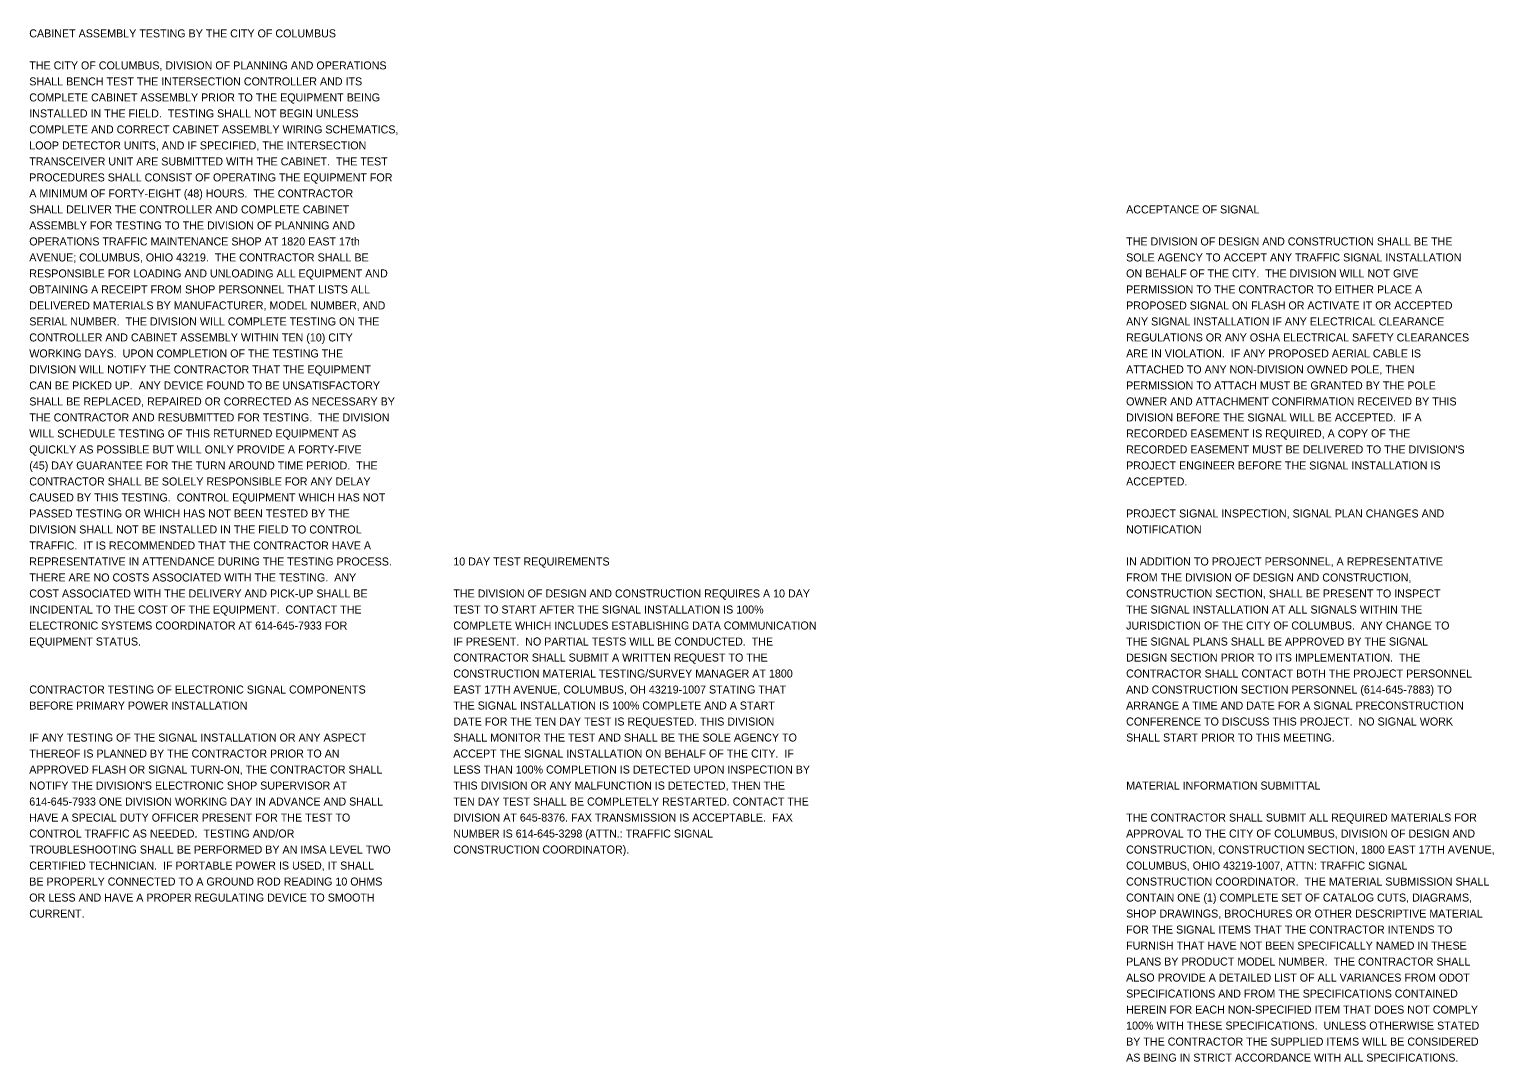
# Model space of a CAD drawing. Extents: x -62 to 50, y -16 to 14.
# Drawn here: x -62.28 to -36.65, y -4.43 to 13.63 of the extents above; entities that cross this region are included whole.
import ezdxf

# ---------------------------------------------------------------- set-up
doc = ezdxf.new("R2010")
doc.units = 0
doc.layers.add('SH_Text', color=7, linetype='Continuous')

msp = doc.modelspace()

# ---------------------------------------------------------------- texts
at = {"layer": 'SH_Text'}
for s, p in [('CABINET ASSEMBLY TESTING BY THE CITY OF COLUMBUS', (-62.277, 13.492)), ('THE CITY OF COLUMBUS, DIVISION OF PLANNING AND OPERATIONS ', (-62.277, 12.932)), ('SHALL BENCH TEST THE INTERSECTION CONTROLLER AND ITS ', (-62.277, 12.652)), ('COMPLETE CABINET ASSEMBLY PRIOR TO THE EQUIPMENT BEING ', (-62.277, 12.372)), ('INSTALLED IN THE FIELD.  TESTING SHALL NOT BEGIN UNLESS ', (-62.277, 12.092)), ('COMPLETE AND CORRECT CABINET ASSEMBLY WIRING SCHEMATICS, ', (-62.277, 11.812)), ('LOOP DETECTOR UNITS, AND IF SPECIFIED, THE INTERSECTION ', (-62.277, 11.532)), ('TRANSCEIVER UNIT ARE SUBMITTED WITH THE CABINET.  THE TEST ', (-62.277, 11.252)), ('PROCEDURES SHALL CONSIST OF OPERATING THE EQUIPMENT FOR ', (-62.277, 10.972)), ('A MINIMUM OF FORTY-EIGHT (48) HOURS.  THE CONTRACTOR ', (-62.277, 10.692)), ('SHALL DELIVER THE CONTROLLER AND COMPLETE CABINET ', (-62.277, 10.412)), ('ACCEPTANCE OF SIGNAL ', (-43.083, 10.412)), ('ASSEMBLY FOR TESTING TO THE DIVISION OF PLANNING AND ', (-62.277, 10.132)), ('OPERATIONS TRAFFIC MAINTENANCE SHOP AT 1820 EAST 17th ', (-62.277, 9.852)), ('THE DIVISION OF DESIGN AND CONSTRUCTION SHALL BE THE ', (-43.083, 9.852)), ('AVENUE; COLUMBUS, OHIO 43219.  THE CONTRACTOR SHALL BE ', (-62.277, 9.572)), ('SOLE AGENCY TO ACCEPT ANY TRAFFIC SIGNAL INSTALLATION ', (-43.083, 9.572)), ('RESPONSIBLE FOR LOADING AND UNLOADING ALL EQUIPMENT AND ', (-62.277, 9.292)), ('ON BEHALF OF THE CITY.  THE DIVISION WILL NOT GIVE ', (-43.083, 9.292)), ('OBTAINING A RECEIPT FROM SHOP PERSONNEL THAT LISTS ALL ', (-62.277, 9.012)), ('PERMISSION TO THE CONTRACTOR TO EITHER PLACE A ', (-43.083, 9.012)), ('DELIVERED MATERIALS BY MANUFACTURER, MODEL NUMBER, AND ', (-62.277, 8.732)), ('PROPOSED SIGNAL ON FLASH OR ACTIVATE IT OR ACCEPTED ', (-43.083, 8.732)), ('SERIAL NUMBER.  THE DIVISION WILL COMPLETE TESTING ON THE ', (-62.277, 8.452)), ('ANY SIGNAL INSTALLATION IF ANY ELECTRICAL CLEARANCE ', (-43.083, 8.452)), ('CONTROLLER AND CABINET ASSEMBLY WITHIN TEN (10) CITY ', (-62.277, 8.172)), ('REGULATIONS OR ANY OSHA ELECTRICAL SAFETY CLEARANCES ', (-43.083, 8.172)), ('WORKING DAYS.  UPON COMPLETION OF THE TESTING THE ', (-62.277, 7.892)), ('ARE IN VIOLATION.  IF ANY PROPOSED AERIAL CABLE IS ', (-43.083, 7.892)), ('DIVISION WILL NOTIFY THE CONTRACTOR THAT THE EQUIPMENT ', (-62.277, 7.612)), ('ATTACHED TO ANY NON-DIVISION OWNED POLE, THEN ', (-43.083, 7.612)), ('CAN BE PICKED UP.  ANY DEVICE FOUND TO BE UNSATISFACTORY ', (-62.277, 7.332)), ('PERMISSION TO ATTACH MUST BE GRANTED BY THE POLE ', (-43.083, 7.332)), ('SHALL BE REPLACED, REPAIRED OR CORRECTED AS NECESSARY BY ', (-62.277, 7.052)), ('OWNER AND ATTACHMENT CONFIRMATION RECEIVED BY THIS ', (-43.083, 7.052)), ('THE CONTRACTOR AND RESUBMITTED FOR TESTING.  THE DIVISION ', (-62.277, 6.772)), ('DIVISION BEFORE THE SIGNAL WILL BE ACCEPTED.  IF A ', (-43.083, 6.772)), ('WILL SCHEDULE TESTING OF THIS RETURNED EQUIPMENT AS ', (-62.277, 6.492)), ('RECORDED EASEMENT IS REQUIRED, A COPY OF THE ', (-43.083, 6.492)), ('QUICKLY AS POSSIBLE BUT WILL ONLY PROVIDE A FORTY-FIVE ', (-62.277, 6.212)), ("RECORDED EASEMENT MUST BE DELIVERED TO THE DIVISION'S ", (-43.083, 6.212)), ('(45) DAY GUARANTEE FOR THE TURN AROUND TIME PERIOD.  THE ', (-62.277, 5.932)), ('PROJECT ENGINEER BEFORE THE SIGNAL INSTALLATION IS ', (-43.083, 5.932)), ('CONTRACTOR SHALL BE SOLELY RESPONSIBLE FOR ANY DELAY ', (-62.277, 5.652)), ('ACCEPTED.  ', (-43.083, 5.652)), ('CAUSED BY THIS TESTING.  CONTROL EQUIPMENT WHICH HAS NOT ', (-62.277, 5.372)), ('PASSED TESTING OR WHICH HAS NOT BEEN TESTED BY THE ', (-62.277, 5.092)), ('PROJECT SIGNAL INSPECTION, SIGNAL PLAN CHANGES AND ', (-43.083, 5.092)), ('DIVISION SHALL NOT BE INSTALLED IN THE FIELD TO CONTROL ', (-62.277, 4.812)), ('NOTIFICATION', (-43.083, 4.812)), ('TRAFFIC.  IT IS RECOMMENDED THAT THE CONTRACTOR HAVE A ', (-62.277, 4.532)), ('REPRESENTATIVE IN ATTENDANCE DURING THE TESTING PROCESS.  ', (-62.277, 4.252)), ('10 DAY TEST REQUIREMENTS', (-54.857, 4.252)), ('IN ADDITION TO PROJECT PERSONNEL, A REPRESENTATIVE ', (-43.083, 4.252)), ('THERE ARE NO COSTS ASSOCIATED WITH THE TESTING.  ANY ', (-62.277, 3.972)), ('FROM THE DIVISION OF DESIGN AND CONSTRUCTION, ', (-43.083, 3.972)), ('COST ASSOCIATED WITH THE DELIVERY AND PICK-UP SHALL BE ', (-62.277, 3.692)), ('THE DIVISION OF DESIGN AND CONSTRUCTION REQUIRES A 10 DAY ', (-54.857, 3.692)), ('CONSTRUCTION SECTION, SHALL BE PRESENT TO INSPECT ', (-43.083, 3.692)), ('INCIDENTAL TO THE COST OF THE EQUIPMENT.  CONTACT THE ', (-62.277, 3.412)), ('TEST TO START AFTER THE SIGNAL INSTALLATION IS 100% ', (-54.857, 3.412)), ('THE SIGNAL INSTALLATION AT ALL SIGNALS WITHIN THE ', (-43.083, 3.412)), ('ELECTRONIC SYSTEMS COORDINATOR AT 614-645-7933 FOR ', (-62.277, 3.132)), ('COMPLETE WHICH INCLUDES ESTABLISHING DATA COMMUNICATION ', (-54.857, 3.132)), ('JURISDICTION OF THE CITY OF COLUMBUS.  ANY CHANGE TO ', (-43.083, 3.132)), ('EQUIPMENT STATUS.', (-62.277, 2.852)), ('IF PRESENT.  NO PARTIAL TESTS WILL BE CONDUCTED.  THE ', (-54.857, 2.852)), ('THE SIGNAL PLANS SHALL BE APPROVED BY THE SIGNAL ', (-43.083, 2.852)), ('CONTRACTOR SHALL SUBMIT A WRITTEN REQUEST TO THE ', (-54.857, 2.572)), ('DESIGN SECTION PRIOR TO ITS IMPLEMENTATION.  THE ', (-43.083, 2.572)), ('CONSTRUCTION MATERIAL TESTING/SURVEY MANAGER AT 1800 ', (-54.857, 2.292)), ('CONTRACTOR SHALL CONTACT BOTH THE PROJECT PERSONNEL ', (-43.083, 2.292)), ('CONTRACTOR TESTING OF ELECTRONIC SIGNAL COMPONENTS ', (-62.277, 2.012)), ('EAST 17TH AVENUE, COLUMBUS, OH 43219-1007 STATING THAT ', (-54.857, 2.012)), ('AND CONSTRUCTION SECTION PERSONNEL (614-645-7883) TO ', (-43.083, 2.012)), ('BEFORE PRIMARY POWER INSTALLATION', (-62.277, 1.732)), ('THE SIGNAL INSTALLATION IS 100% COMPLETE AND A START ', (-54.857, 1.732)), ('ARRANGE A TIME AND DATE FOR A SIGNAL PRECONSTRUCTION ', (-43.083, 1.732)), ('DATE FOR THE TEN DAY TEST IS REQUESTED. THIS DIVISION ', (-54.857, 1.452)), ('CONFERENCE TO DISCUSS THIS PROJECT.  NO SIGNAL WORK ', (-43.083, 1.452)), ('IF ANY TESTING OF THE SIGNAL INSTALLATION OR ANY ASPECT ', (-62.277, 1.172)), ('SHALL MONITOR THE TEST AND SHALL BE THE SOLE AGENCY TO ', (-54.857, 1.172)), ('SHALL START PRIOR TO THIS MEETING.', (-43.083, 1.172)), ('THEREOF IS PLANNED BY THE CONTRACTOR PRIOR TO AN ', (-62.277, 0.892)), ('ACCEPT THE SIGNAL INSTALLATION ON BEHALF OF THE CITY.  IF ', (-54.857, 0.892)), ('APPROVED FLASH OR SIGNAL TURN-ON, THE CONTRACTOR SHALL ', (-62.277, 0.612)), ('LESS THAN 100% COMPLETION IS DETECTED UPON INSPECTION BY ', (-54.857, 0.612)), ("NOTIFY THE DIVISION'S ELECTRONIC SHOP SUPERVISOR AT ", (-62.277, 0.332)), ('THIS DIVISION OR ANY MALFUNCTION IS DETECTED, THEN THE ', (-54.857, 0.332)), ('MATERIAL INFORMATION SUBMITTAL', (-43.083, 0.332)), ('614-645-7933 ONE DIVISION WORKING DAY IN ADVANCE AND SHALL ', (-62.277, 0.052)), ('TEN DAY TEST SHALL BE COMPLETELY RESTARTED. CONTACT THE ', (-54.857, 0.052)), ('HAVE A SPECIAL DUTY OFFICER PRESENT FOR THE TEST TO ', (-62.277, -0.228)), ('DIVISION AT 645-8376. FAX TRANSMISSION IS ACCEPTABLE.  FAX ', (-54.857, -0.228)), ('THE CONTRACTOR SHALL SUBMIT ALL REQUIRED MATERIALS FOR ', (-43.083, -0.228)), ('CONTROL TRAFFIC AS NEEDED.  TESTING AND/OR ', (-62.277, -0.508)), ('NUMBER IS 614-645-3298 (ATTN.: TRAFFIC SIGNAL ', (-54.857, -0.508)), ('APPROVAL TO THE CITY OF COLUMBUS, DIVISION OF DESIGN AND ', (-43.083, -0.508)), ('TROUBLESHOOTING SHALL BE PERFORMED BY AN IMSA LEVEL TWO ', (-62.277, -0.788)), ('CONSTRUCTION COORDINATOR).', (-54.857, -0.788)), ('CONSTRUCTION, CONSTRUCTION SECTION, 1800 EAST 17TH AVENUE, ', (-43.083, -0.788)), ('CERTIFIED TECHNICIAN.  IF PORTABLE POWER IS USED, IT SHALL ', (-62.277, -1.068)), ('COLUMBUS, OHIO 43219-1007, ATTN: TRAFFIC SIGNAL ', (-43.083, -1.068)), ('BE PROPERLY CONNECTED TO A GROUND ROD READING 10 OHMS ', (-62.277, -1.348)), ('CONSTRUCTION COORDINATOR.  THE MATERIAL SUBMISSION SHALL ', (-43.083, -1.348)), ('OR LESS AND HAVE A PROPER REGULATING DEVICE TO SMOOTH ', (-62.277, -1.628)), ('CONTAIN ONE (1) COMPLETE SET OF CATALOG CUTS, DIAGRAMS, ', (-43.083, -1.628)), ('CURRENT.', (-62.277, -1.908)), ('SHOP DRAWINGS, BROCHURES OR OTHER DESCRIPTIVE MATERIAL ', (-43.083, -1.908)), ('FOR THE SIGNAL ITEMS THAT THE CONTRACTOR INTENDS TO ', (-43.083, -2.188)), ('FURNISH THAT HAVE NOT BEEN SPECIFICALLY NAMED IN THESE ', (-43.083, -2.468)), ('PLANS BY PRODUCT MODEL NUMBER.  THE CONTRACTOR SHALL ', (-43.083, -2.748)), ('ALSO PROVIDE A DETAILED LIST OF ALL VARIANCES FROM ODOT ', (-43.083, -3.028)), ('SPECIFICATIONS AND FROM THE SPECIFICATIONS CONTAINED ', (-43.083, -3.308)), ('HEREIN FOR EACH NON-SPECIFIED ITEM THAT DOES NOT COMPLY ', (-43.083, -3.588)), ('100% WITH THESE SPECIFICATIONS.  UNLESS OTHERWISE STATED ', (-43.083, -3.868)), ('BY THE CONTRACTOR THE SUPPLIED ITEMS WILL BE CONSIDERED ', (-43.083, -4.148)), ('AS BEING IN STRICT ACCORDANCE WITH ALL SPECIFICATIONS.', (-43.083, -4.428))]:
    msp.add_text(s, height=0.14, dxfattribs=at).set_placement(p)

doc.saveas('drawing.dxf')
